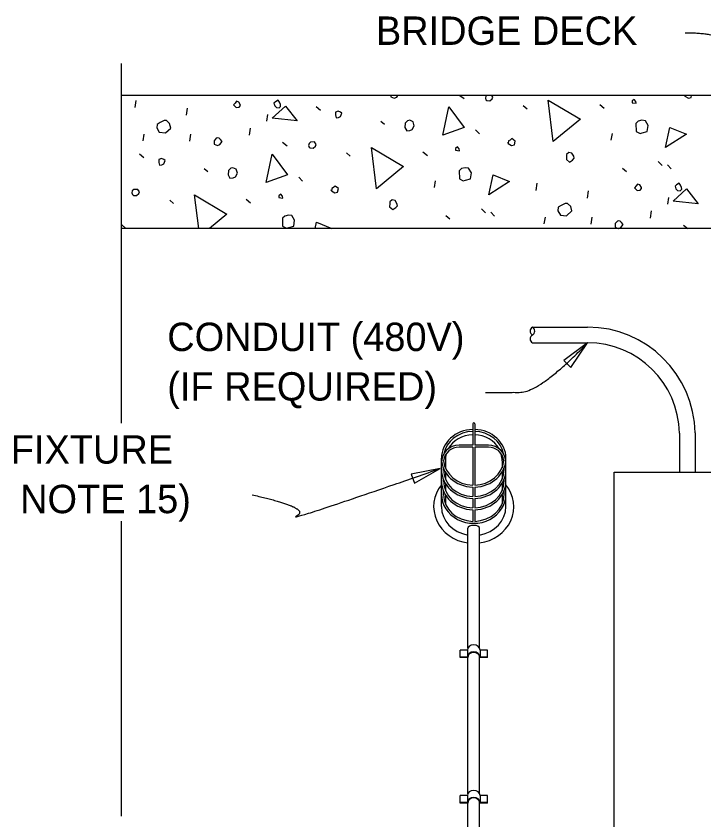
# Model space of a CAD drawing. Extents: x -1660015.2 to -1659984.9, y 2580594.2 to 2580616.7.
# Drawn here: x -1660002.937 to -1659999.271, y 2580610.338 to 2580614.62 of the extents above; entities that cross this region are included whole.
import ezdxf

# ---------------------------------------------------------------- set-up
doc = ezdxf.new("R2010")
doc.units = 0
for name, color, linetype in [('Default', 7, 'Continuous'), ('Miscellaneous', 7, 'Continuous'), ('Miscellaneous3', 7, 'Continuous'), ('PlotBorder_dp', 7, 'Continuous'), ('SheetLines_dp', 7, 'Continuous'), ('SteelGirder', 7, 'Continuous')]:
    doc.layers.add(name, color=color, linetype=linetype)

msp = doc.modelspace()

# ---------------------------------------------------------------- linework, layer by layer
at = {"layer": 'Default'}
for p, q in [((-1660000.1851, 2580612.9626), (-1659999.8911, 2580612.9626)), ((-1660000.1854, 2580612.8794), (-1659999.8911, 2580612.8794)), ((-1660000.5031, 2580612.4482), (-1660000.5031, 2580612.3343)), ((-1660000.4927, 2580612.4482), (-1660000.4927, 2580612.3343)), ((-1659999.4016, 2580612.3985), (-1659999.4016, 2580612.1902)), ((-1659999.3183, 2580612.3993), (-1659999.3183, 2580612.1902)), ((-1660000.5031, 2580612.3343), (-1660000.5761, 2580612.3343)), ((-1660000.5031, 2580612.3239), (-1660000.5761, 2580612.3239)), ((-1660000.5031, 2580612.3239), (-1660000.5031, 2580612.1208)), ((-1660000.4198, 2580612.3343), (-1660000.4927, 2580612.3343)), ((-1660000.4927, 2580612.3239), (-1660000.4927, 2580612.1208)), ((-1660000.4198, 2580612.3239), (-1660000.4927, 2580612.3239)), ((-1660000.6698, 2580612.0068), (-1660000.6698, 2580612.2642)), ((-1660000.3261, 2580612.0068), (-1660000.3261, 2580612.2642)), ((-1660000.6594, 2580612.2039), (-1660000.6594, 2580612.2115)), ((-1660000.3365, 2580612.2039), (-1660000.3365, 2580612.2115)), ((-1660000.6594, 2580612.1436), (-1660000.6594, 2580612.1512)), ((-1660000.3365, 2580612.1436), (-1660000.3365, 2580612.1512)), ((-1660000.6594, 2580612.0717), (-1660000.6594, 2580612.0909)), ((-1660000.5031, 2580612.1104), (-1660000.5031, 2580612.0605)), ((-1660000.4927, 2580612.1104), (-1660000.4927, 2580612.0605)), ((-1660000.3365, 2580612.0717), (-1660000.3365, 2580612.0909)), ((-1660000.5031, 2580612.0501), (-1660000.5031, 2580612.0002)), ((-1660000.4927, 2580612.0501), (-1660000.4927, 2580612.0002)), ((-1660000.5031, 2580611.9898), (-1660000.5031, 2580611.9283)), ((-1660000.4927, 2580611.9898), (-1660000.4927, 2580611.9283)), ((-1660000.5291, 2580611.2525), (-1660000.5291, 2580611.8926)), ((-1660000.4667, 2580611.2525), (-1660000.4667, 2580611.8926)), ((-1660000.5291, 2580610.4775), (-1660000.5291, 2580611.2027)), ((-1660000.4667, 2580610.4775), (-1660000.4667, 2580611.2027)), ((-1660000.5291, 2580609.6642), (-1660000.5291, 2580610.4278)), ((-1660000.4667, 2580609.6642), (-1660000.4667, 2580610.4278))]:
    msp.add_line(p, q, dxfattribs=at)
msp.add_lwpolyline([(-1659999.6133, 2580609.4652), (-1659999.7488, 2580609.4652), (-1659999.7488, 2580612.1902), (-1659998.7488, 2580612.1902), (-1659998.7488, 2580609.4652), (-1659998.8843, 2580609.4652)], dxfattribs=at)
for centre, radius, start, end in [((-1660000.1735, 2580612.9418), 0.0238, 119.0026, 240.9973), ((-1660000.1966, 2580612.9418), 0.0238, 299.0029, 60.997), ((-1659999.8911, 2580612.3898), 0.5729, 0.9435, 90), ((-1660000.1735, 2580612.9001), 0.0238, 119.0027, 240.0206), ((-1659999.8911, 2580612.3898), 0.4896, 1.0206, 90), ((-1660000.4979, 2580612.4482), 0.0052, 0.0584, 180.0007), ((-1660000.5761, 2580612.2406), 0.0937, 90, 180), ((-1660000.5761, 2580612.2406), 0.0833, 90, 172.7392), ((-1660000.4198, 2580612.2406), 0.0937, 0, 90), ((-1660000.4198, 2580612.2406), 0.0833, 7.2613, 90)]:
    msp.add_arc(centre, radius, start, end, dxfattribs=at)
for centre, major_axis, ratio, start_param, end_param in [((-1660000.4979, 2580612.2642), (-0.1718, 0), 0.895384, 4.742653, 7.823718), ((-1660000.4979, 2580612.2642), (-0.1614, 0), 0.888645, 4.744603, 6.130919), ((-1660000.4979, 2580612.2642), (-0.1718, 0), 0.895384, 3.141593, 4.682125), ((-1660000.4979, 2580612.2642), (-0.1614, 0), 0.888645, 3.306024, 4.680175), ((-1660000.4979, 2580612.2642), (-0.1614, 0), 0.888645, 0.090994, 1.538583), ((-1660000.4979, 2580612.2642), (-0.1718, 0), 0.895384, 1.60106, 3.141593), ((-1660000.4979, 2580612.2642), (-0.1614, 0), 0.888645, 1.60301, 3.050599), ((-1660000.4979, 2580612.2039), (-0.1718, 0), 0.895384, 0, 1.540533), ((-1660000.4979, 2580612.2039), (-0.1614, 0), 0.888645, 0.000093, 1.538583), ((-1660000.4979, 2580612.2039), (-0.1718, 0), 0.895384, 1.60106, 3.141593), ((-1660000.4979, 2580612.2039), (-0.1614, 0), 0.888645, 1.60301, 3.141686), ((-1660000.4979, 2580612.0068), (-0.2135, 0), 0.915812, 5.647609, 7.707355), ((-1660000.4979, 2580612.1436), (-0.1718, 0), 0.895384, 0, 1.540533), ((-1660000.4979, 2580612.1436), (-0.1614, 0), 0.888645, 0.000093, 1.538583), ((-1660000.4979, 2580612.1436), (-0.1614, 0), 0.888645, 1.60301, 3.141686), ((-1660000.4979, 2580612.1436), (-0.1718, 0), 0.895384, 1.60106, 3.141593), ((-1660000.4979, 2580612.0068), (-0.2135, 0), 0.915812, 1.717423, 3.777169), ((-1660000.4979, 2580612.0717), (-0.1718, 0), 0.895384, 0, 3.141593), ((-1660000.4979, 2580612.0717), (-0.1614, 0), 0.888645, 0.000093, 1.538583), ((-1660000.4979, 2580612.0717), (-0.1614, 0), 0.888645, 1.60301, 3.141686), ((-1660000.4979, 2580612.0068), (-0.1718, 0), 0.895384, 6.283173, 7.671415), ((-1660000.4979, 2580612.0068), (-0.1718, 0), 0.895384, 1.753362, 3.141593), ((-1660000.4979, 2580611.8926), (-0.0312, 0), 0.446008, 3.14248, 6.283159)]:
    msp.add_ellipse(centre, major_axis=major_axis, ratio=ratio, start_param=start_param, end_param=end_param, dxfattribs=at)
at = {"layer": 'Miscellaneous'}
for p, q in [((-1660000.5712, 2580614.197), (-1660000.5494, 2580614.181)), ((-1660002.3018, 2580614.1333), (-1660002.2964, 2580614.171)), ((-1660001.3376, 2580614.138), (-1660001.3143, 2580614.1184)), ((-1660000.234, 2580614.1439), (-1660000.2137, 2580614.126)), ((-1659999.8266, 2580614.1495), (-1659999.8033, 2580614.1299)), ((-1660002.0294, 2580614.0924), (-1660002.024, 2580614.1301)), ((-1660001.6013, 2580614.0596), (-1660001.5953, 2580614.0949)), ((-1660000.9931, 2580614.0595), (-1660000.9734, 2580614.0441)), ((-1660001.6929, 2580613.9859), (-1660001.6874, 2580614.0236)), ((-1660000.489, 2580614.0134), (-1660000.468, 2580613.9932)), ((-1660002.2594, 2580613.9558), (-1660002.2533, 2580613.991)), ((-1660002.0101, 2580613.9527), (-1660002.0047, 2580613.9904)), ((-1659999.7652, 2580613.9589), (-1659999.7591, 2580613.9942)), ((-1660001.517, 2580613.9476), (-1660001.4912, 2580613.9287)), ((-1660002.2794, 2580613.8857), (-1660002.256, 2580613.8661)), ((-1660001.1758, 2580613.8915), (-1660001.1555, 2580613.8737)), ((-1660000.7684, 2580613.8972), (-1660000.745, 2580613.8775)), ((-1659999.5147, 2580613.8449), (-1659999.4937, 2580613.8246)), ((-1660001.9349, 2580613.8072), (-1660001.9152, 2580613.7918)), ((-1659999.7045, 2580613.8095), (-1659999.6842, 2580613.7917)), ((-1659999.4658, 2580613.8269), (-1659999.4449, 2580613.8066)), ((-1660001.4308, 2580613.7611), (-1660001.4098, 2580613.7408)), ((-1660000.707, 2580613.7066), (-1660000.7009, 2580613.7418)), ((-1660000.1646, 2580613.6914), (-1660000.1592, 2580613.7291)), ((-1659999.8922, 2580613.6505), (-1659999.8868, 2580613.6882)), ((-1660002.1176, 2580613.6392), (-1660002.0973, 2580613.6213)), ((-1660001.7102, 2580613.6448), (-1660001.6868, 2580613.6252)), ((-1659999.4641, 2580613.6177), (-1659999.4581, 2580613.653)), ((-1660000.4564, 2580613.5925), (-1660000.4355, 2580613.5723)), ((-1659999.5557, 2580613.544), (-1659999.5502, 2580613.5817)), ((-1660000.6463, 2580613.5572), (-1660000.6259, 2580613.5393)), ((-1660000.4076, 2580613.5745), (-1660000.3867, 2580613.5543)), ((-1660000.1222, 2580613.5139), (-1660000.1161, 2580613.5491)), ((-1659999.8729, 2580613.5108), (-1659999.8675, 2580613.5485)), ((-1660002.3725, 2580613.5087), (-1660002.3517, 2580613.4886)), ((-1659999.3798, 2580613.5057), (-1659999.3565, 2580613.4886)), ((-1660001.6428, 2580613.4886), (-1660001.6427, 2580613.4895)), ((-1660000.6489, 2580612.2503), (-1660000.6489, 2580612.2133)), ((-1660000.347, 2580612.2503), (-1660000.347, 2580612.2133)), ((-1660000.6489, 2580612.1907), (-1660000.6489, 2580612.153)), ((-1660000.347, 2580612.1907), (-1660000.347, 2580612.153)), ((-1660000.6489, 2580612.1304), (-1660000.6489, 2580612.0927)), ((-1660000.347, 2580612.1304), (-1660000.347, 2580612.0927)), ((-1660000.6489, 2580612.0701), (-1660000.6489, 2580612.0208)), ((-1660000.347, 2580612.0701), (-1660000.347, 2580612.0208))]:
    msp.add_line(p, q, dxfattribs=at)
for points in [[(-1660000.94, 2580614.197), (-1660000.9401, 2580614.1902), (-1660000.9224, 2580614.182), (-1660000.9085, 2580614.1883), (-1660000.9024, 2580614.197)], [(-1660000.4302, 2580614.197), (-1660000.4338, 2580614.1939), (-1660000.436, 2580614.1829), (-1660000.4335, 2580614.1733)], [(-1660000.4335, 2580614.1733), (-1660000.4273, 2580614.1697), (-1660000.4115, 2580614.1688), (-1660000.399, 2580614.1799), (-1660000.3961, 2580614.1884), (-1660000.4018, 2580614.197)], [(-1659999.3721, 2580614.197), (-1659999.3725, 2580614.1935), (-1659999.3735, 2580614.197)], [(-1659999.3725, 2580614.1935), (-1659999.3542, 2580614.1829), (-1659999.3397, 2580614.1868), (-1659999.337, 2580614.197)], [(-1660001.7775, 2580614.147), (-1660001.7633, 2580614.1327), (-1660001.7481, 2580614.1342), (-1660001.7404, 2580614.144), (-1660001.7417, 2580614.1488), (-1660001.7504, 2580614.162), (-1660001.762, 2580614.1667), (-1660001.7697, 2580614.1568), (-1660001.7775, 2580614.147)], [(-1660001.5719, 2580614.0753), (-1660001.5014, 2580614.1407), (-1660001.4388, 2580614.0617), (-1660001.5719, 2580614.0753)], [(-1660001.5584, 2580614.141), (-1660001.5486, 2580614.1333), (-1660001.5352, 2580614.1317), (-1660001.5269, 2580614.1391), (-1660001.527, 2580614.1494), (-1660001.5327, 2580614.1608), (-1660001.5408, 2580614.1716), (-1660001.554, 2580614.1629), (-1660001.5623, 2580614.1555), (-1660001.5584, 2580614.141)], [(-1660000.6625, 2580613.9851), (-1660000.6305, 2580614.136), (-1660000.5492, 2580614.0258), (-1660000.6625, 2580613.9851)], [(-1660000.0737, 2580613.9513), (-1660000.1017, 2580614.1716), (-1659999.9296, 2580614.0702), (-1660000.0737, 2580613.9513)], [(-1659999.6527, 2580614.1573), (-1659999.6315, 2580614.1552), (-1659999.634, 2580614.1649), (-1659999.6421, 2580614.1757), (-1659999.6529, 2580614.1676), (-1659999.6527, 2580614.1573)], [(-1660001.235, 2580614.0931), (-1660001.2311, 2580614.0786), (-1660001.2184, 2580614.0794), (-1660001.207, 2580614.0851), (-1660001.2012, 2580614.1021), (-1660001.208, 2580614.1081), (-1660001.2196, 2580614.1127), (-1660001.2341, 2580614.1089), (-1660001.235, 2580614.0931)], [(-1660002.1872, 2580614.0243), (-1660002.1734, 2580614.0021), (-1660002.1412, 2580613.9978), (-1660002.1119, 2580614.0237), (-1660002.1184, 2580614.0479), (-1660002.1357, 2580614.064), (-1660002.1484, 2580614.0631), (-1660002.1688, 2580614.0525), (-1660002.1844, 2580614.0431), (-1660002.1872, 2580614.0243)], [(-1660000.8638, 2580614.0502), (-1660000.8652, 2580614.0265), (-1660000.8552, 2580614.0085), (-1660000.8376, 2580614.0106), (-1660000.8262, 2580614.0163), (-1660000.8156, 2580614.0346), (-1660000.8214, 2580614.0564), (-1660000.8391, 2580614.0646), (-1660000.8512, 2580614.0613), (-1660000.8638, 2580614.0502)], [(-1659999.6339, 2580614.0484), (-1659999.6326, 2580614.0048), (-1659999.6118, 2580613.9948), (-1659999.5997, 2580613.9981), (-1659999.5731, 2580614.0052), (-1659999.5688, 2580614.0374), (-1659999.5832, 2580614.062), (-1659999.602, 2580614.0647), (-1659999.6214, 2580614.0596), (-1659999.6339, 2580614.0484)], [(-1659999.4753, 2580613.9201), (-1659999.4522, 2580614.0272), (-1659999.3649, 2580613.9911), (-1659999.4753, 2580613.9201)], [(-1660001.8816, 2580613.9561), (-1660001.8819, 2580613.9379), (-1660001.8642, 2580613.9297), (-1660001.8503, 2580613.936), (-1660001.8391, 2580613.9519), (-1660001.8471, 2580613.9627), (-1660001.8539, 2580613.9687), (-1660001.8648, 2580613.9709), (-1660001.8697, 2580613.9696), (-1660001.8816, 2580613.9561)], [(-1660000.3143, 2580613.9412), (-1660000.296, 2580613.9306), (-1660000.2815, 2580613.9345), (-1660000.2763, 2580613.954), (-1660000.2954, 2580613.967), (-1660000.3037, 2580613.9596), (-1660000.3127, 2580613.9546), (-1660000.3143, 2580613.9412), (-1660000.3156, 2580613.946)], [(-1660001.3752, 2580613.9209), (-1660001.3691, 2580613.9174), (-1660001.3533, 2580613.9164), (-1660001.3408, 2580613.9276), (-1660001.3379, 2580613.9361), (-1660001.3466, 2580613.9493), (-1660001.3672, 2580613.9489), (-1660001.3756, 2580613.9415), (-1660001.3778, 2580613.9306), (-1660001.3752, 2580613.9209)], [(-1660000.5945, 2580613.9049), (-1660000.5732, 2580613.9029), (-1660000.5758, 2580613.9125), (-1660000.5839, 2580613.9233), (-1660000.5947, 2580613.9152), (-1660000.5945, 2580613.9049)], [(-1660001.6043, 2580613.7327), (-1660001.5723, 2580613.8836), (-1660001.491, 2580613.7734), (-1660001.6043, 2580613.7327)], [(-1660001.0155, 2580613.6989), (-1660001.0435, 2580613.9192), (-1660000.8714, 2580613.8178), (-1660001.0155, 2580613.6989)], [(-1660000.0039, 2580613.8742), (-1660000.0042, 2580613.856), (-1659999.9876, 2580613.8424), (-1659999.972, 2580613.8517), (-1659999.9619, 2580613.8622), (-1659999.9651, 2580613.8743), (-1659999.9745, 2580613.8899), (-1659999.9909, 2580613.8933), (-1660000.0034, 2580613.8821), (-1660000.0039, 2580613.8742)], [(-1660002.1768, 2580613.8407), (-1660002.1729, 2580613.8262), (-1660002.1602, 2580613.8271), (-1660002.1488, 2580613.8327), (-1660002.143, 2580613.8498), (-1660002.1497, 2580613.8557), (-1660002.1614, 2580613.8604), (-1660002.1758, 2580613.8565), (-1660002.1768, 2580613.8407)], [(-1660001.8055, 2580613.7978), (-1660001.807, 2580613.7742), (-1660001.797, 2580613.7561), (-1660001.7794, 2580613.7583), (-1660001.768, 2580613.7639), (-1660001.7574, 2580613.7823), (-1660001.7632, 2580613.804), (-1660001.7809, 2580613.8122), (-1660001.793, 2580613.809), (-1660001.8055, 2580613.7978)], [(-1660000.5757, 2580613.7961), (-1660000.5743, 2580613.7525), (-1660000.5536, 2580613.7425), (-1660000.5415, 2580613.7457), (-1660000.5149, 2580613.7528), (-1660000.5106, 2580613.7851), (-1660000.525, 2580613.8097), (-1660000.5438, 2580613.8124), (-1660000.5631, 2580613.8072), (-1660000.5757, 2580613.7961)], [(-1660000.4171, 2580613.6678), (-1660000.394, 2580613.7749), (-1660000.3067, 2580613.7388), (-1660000.4171, 2580613.6678)], [(-1660001.2561, 2580613.6888), (-1660001.2377, 2580613.6782), (-1660001.2232, 2580613.6821), (-1660001.2181, 2580613.7016), (-1660001.2371, 2580613.7146), (-1660001.2455, 2580613.7072), (-1660001.2545, 2580613.7022), (-1660001.2561, 2580613.6888), (-1660001.2574, 2580613.6937)], [(-1659999.6403, 2580613.7051), (-1659999.6261, 2580613.6908), (-1659999.6109, 2580613.6923), (-1659999.6032, 2580613.7021), (-1659999.6045, 2580613.7069), (-1659999.6132, 2580613.7201), (-1659999.6248, 2580613.7248), (-1659999.6325, 2580613.7149), (-1659999.6403, 2580613.7051)], [(-1659999.4212, 2580613.6991), (-1659999.4114, 2580613.6914), (-1659999.398, 2580613.6898), (-1659999.3897, 2580613.6972), (-1659999.3898, 2580613.7075), (-1659999.3955, 2580613.7189), (-1659999.4036, 2580613.7297), (-1659999.4168, 2580613.721), (-1659999.4251, 2580613.7136), (-1659999.4212, 2580613.6991)], [(-1660002.317, 2580613.6686), (-1660002.3109, 2580613.665), (-1660002.2951, 2580613.6641), (-1660002.2826, 2580613.6752), (-1660002.2797, 2580613.6837), (-1660002.2884, 2580613.6969), (-1660002.309, 2580613.6966), (-1660002.3174, 2580613.6892), (-1660002.3196, 2580613.6782), (-1660002.317, 2580613.6686)], [(-1660001.9626, 2580613.4886), (-1660001.9853, 2580613.6669), (-1660001.8132, 2580613.5655), (-1660001.9064, 2580613.4886)], [(-1660001.5363, 2580613.6526), (-1660001.515, 2580613.6505), (-1660001.5176, 2580613.6602), (-1660001.5257, 2580613.671), (-1660001.5364, 2580613.6629), (-1660001.5363, 2580613.6526)], [(-1659999.4347, 2580613.6334), (-1659999.3642, 2580613.6988), (-1659999.3016, 2580613.6198), (-1659999.4347, 2580613.6334)], [(-1660000.9457, 2580613.6219), (-1660000.946, 2580613.6037), (-1660000.9294, 2580613.59), (-1660000.9138, 2580613.5994), (-1660000.9037, 2580613.6099), (-1660000.9069, 2580613.6219), (-1660000.9162, 2580613.6375), (-1660000.9327, 2580613.6409), (-1660000.9452, 2580613.6298), (-1660000.9457, 2580613.6219)], [(-1660000.05, 2580613.5824), (-1660000.0362, 2580613.5602), (-1660000.004, 2580613.5559), (-1659999.9747, 2580613.5818), (-1659999.9812, 2580613.606), (-1659999.9985, 2580613.6221), (-1660000.0112, 2580613.6212), (-1660000.0316, 2580613.6106), (-1660000.0472, 2580613.6012), (-1660000.05, 2580613.5824)], [(-1660001.5175, 2580613.5437), (-1660001.5161, 2580613.5001), (-1660001.4953, 2580613.4901), (-1660001.4833, 2580613.4934), (-1660001.4567, 2580613.5005), (-1660001.4524, 2580613.5327), (-1660001.4667, 2580613.5573), (-1660001.4856, 2580613.5601), (-1660001.5049, 2580613.5549), (-1660001.5175, 2580613.5437)], [(-1660001.3431, 2580613.4886), (-1660001.3358, 2580613.5225), (-1660001.2537, 2580613.4886)], [(-1659999.7444, 2580613.5141), (-1659999.7447, 2580613.4959), (-1659999.7287, 2580613.4886)], [(-1659999.7251, 2580613.4886), (-1659999.7131, 2580613.4941), (-1659999.7019, 2580613.51), (-1659999.7099, 2580613.5208), (-1659999.7167, 2580613.5267), (-1659999.7277, 2580613.529), (-1659999.7325, 2580613.5277), (-1659999.7444, 2580613.5141)]]:
    msp.add_lwpolyline(points, dxfattribs=at)
for start_param, end_param in [(1.605229, 2.691201), (0.45306, 1.536364), (2.896336, 3.176025), (6.248753, 6.522968)]:
    msp.add_ellipse((-1660000.4979, 2580612.2549), major_axis=(0.151, 0), ratio=0.895384, start_param=start_param, end_param=end_param, dxfattribs=at)
at = {"layer": 'Miscellaneous3'}
for p, q in [((-1659997.3318, 2580614.197), (-1660002.3746, 2580614.197)), ((-1659997.3318, 2580613.4886), (-1660002.3746, 2580613.4886))]:
    msp.add_line(p, q, dxfattribs=at)
at = {"layer": 'SheetLines_dp'}
for points in [[(-1660002.3746, 2580612.4522), (-1660002.3746, 2580614.3666)], [(-1660002.3746, 2580610.3575), (-1660002.3746, 2580611.93)]]:
    msp.add_lwpolyline(points, dxfattribs=at)
for points in [[(-1659999.8911, 2580612.8794), (-1660000.0185, 2580612.7853), (-1659999.9804, 2580612.7486)], [(-1660000.6763, 2580612.2097), (-1660000.832, 2580612.1805), (-1660000.8137, 2580612.1309)]]:
    msp.add_lwpolyline(points, close=True, dxfattribs=at)
for points in [[(-1659998.8861, 2580614.197), (-1659998.9683, 2580614.3298), (-1659999.0489, 2580614.4326), (-1659999.204, 2580614.5295), (-1659999.3716, 2580614.5295)], [(-1660000.4357, 2580612.6156), (-1660000.3598, 2580612.6156), (-1660000.1455, 2580612.6156), (-1659999.8911, 2580612.8794)], [(-1660001.6792, 2580612.0697), (-1660001.3605, 2580611.999), (-1660001.5224, 2580611.9157), (-1660000.6763, 2580612.2097)]]:
    msp.add_open_spline(points, degree=2, dxfattribs=at)
at = {"layer": 'SteelGirder'}
for p, q in [((-1660000.5314, 2580611.2424), (-1660000.5708, 2580611.2424)), ((-1660000.5708, 2580611.2027), (-1660000.5708, 2580611.2424)), ((-1660000.5314, 2580611.2424), (-1660000.5314, 2580611.205)), ((-1660000.425, 2580611.2424), (-1660000.4644, 2580611.2424)), ((-1660000.4644, 2580611.2424), (-1660000.4644, 2580611.205)), ((-1660000.425, 2580611.2027), (-1660000.425, 2580611.2424)), ((-1660000.5314, 2580611.205), (-1660000.5708, 2580611.205)), ((-1660000.5291, 2580611.2027), (-1660000.5708, 2580611.2027)), ((-1660000.425, 2580611.2027), (-1660000.4667, 2580611.2027)), ((-1660000.425, 2580611.205), (-1660000.4644, 2580611.205)), ((-1660000.5314, 2580610.4674), (-1660000.5708, 2580610.4674)), ((-1660000.5708, 2580610.4278), (-1660000.5708, 2580610.4674)), ((-1660000.5314, 2580610.4674), (-1660000.5314, 2580610.4301)), ((-1660000.425, 2580610.4674), (-1660000.4644, 2580610.4674)), ((-1660000.4644, 2580610.4674), (-1660000.4644, 2580610.4301)), ((-1660000.425, 2580610.4278), (-1660000.425, 2580610.4674)), ((-1660000.5314, 2580610.4301), (-1660000.5708, 2580610.4301)), ((-1660000.5291, 2580610.4278), (-1660000.5708, 2580610.4278)), ((-1660000.425, 2580610.4278), (-1660000.4667, 2580610.4278)), ((-1660000.425, 2580610.4301), (-1660000.4644, 2580610.4301))]:
    msp.add_line(p, q, dxfattribs=at)
for centre, major_axis, ratio, end_param in [((-1660000.4979, 2580611.2424), (-0.0335, 0), 0.830773, 6.282753), ((-1660000.4979, 2580611.205), (-0.0335, 0), 0.830773, 6.282753), ((-1660000.4979, 2580611.2027), (-0.0312, 0), 0.892016, 6.283768), ((-1660000.4979, 2580610.4674), (-0.0335, 0), 0.830773, 6.282753), ((-1660000.4979, 2580610.4301), (-0.0335, 0), 0.830773, 6.282753), ((-1660000.4979, 2580610.4278), (-0.0312, 0), 0.892016, 6.283768)]:
    msp.add_ellipse(centre, major_axis=major_axis, ratio=ratio, start_param=3.141593, end_param=end_param, dxfattribs=at)

# ---------------------------------------------------------------- texts
at = {"layer": 'PlotBorder_dp'}
msp.add_text('BRIDGE DECK', height=0.1512, dxfattribs=at).set_placement((-1660001.0192, 2580614.4665))
at = {"layer": 'SheetLines_dp'}
for s, p in [('CONDUIT (480V)', (-1660002.1311, 2580612.8356)), ('(IF REQUIRED)', (-1660002.1311, 2580612.5716)), ('LED LIGHT FIXTURE ', (-1660004.0659, 2580612.2358)), ('(SEE NOTE 15)', (-1660003.4433, 2580611.9718))]:
    msp.add_text(s, height=0.1512, dxfattribs=at).set_placement(p)

doc.saveas('drawing.dxf')
